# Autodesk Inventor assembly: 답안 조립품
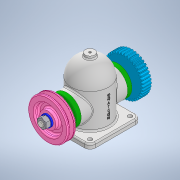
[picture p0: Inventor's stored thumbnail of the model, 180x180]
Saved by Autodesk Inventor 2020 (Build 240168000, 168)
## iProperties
Created: 2021-07
Part Number: 답안 조립품
Document SubType Name: Assembly
Designer: Owner
Author: Owner
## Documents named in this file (14)
- C:\Users\Owner\Desktop\710716V1001\답안 조립품.iam
- C:\Users\Owner\Desktop\710716V1001\본체.ipt
- C:\Users\Owner\Desktop\710716V1001\V-벨트풀리.ipt
- V-벨트풀리.ipt
- C:\Users\Owner\Desktop\710716V1001\너트 M12x1.25.ipt
- C:\Users\Owner\Desktop\710716V1001\베어링 6203.ipt
- C:\Users\Owner\Desktop\710716V1001\볼트 M4.ipt
- C:\Users\Owner\Desktop\710716V1001\부시.ipt
- C:\Users\Owner\Desktop\710716V1001\스퍼기어.ipt
- C:\Users\Owner\Desktop\710716V1001\오일 실 26 38 8.ipt
- C:\Users\Owner\Desktop\710716V1001\와셔 12x24.ipt
- C:\Users\Owner\Desktop\710716V1001\축.ipt
- C:\Users\Owner\Desktop\710716V1001\커버.ipt
- C:\Users\Owner\Desktop\710716V1001\키 5x5x12.ipt
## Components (1 placed, 1 different names)
1. V-벨트풀리:1
